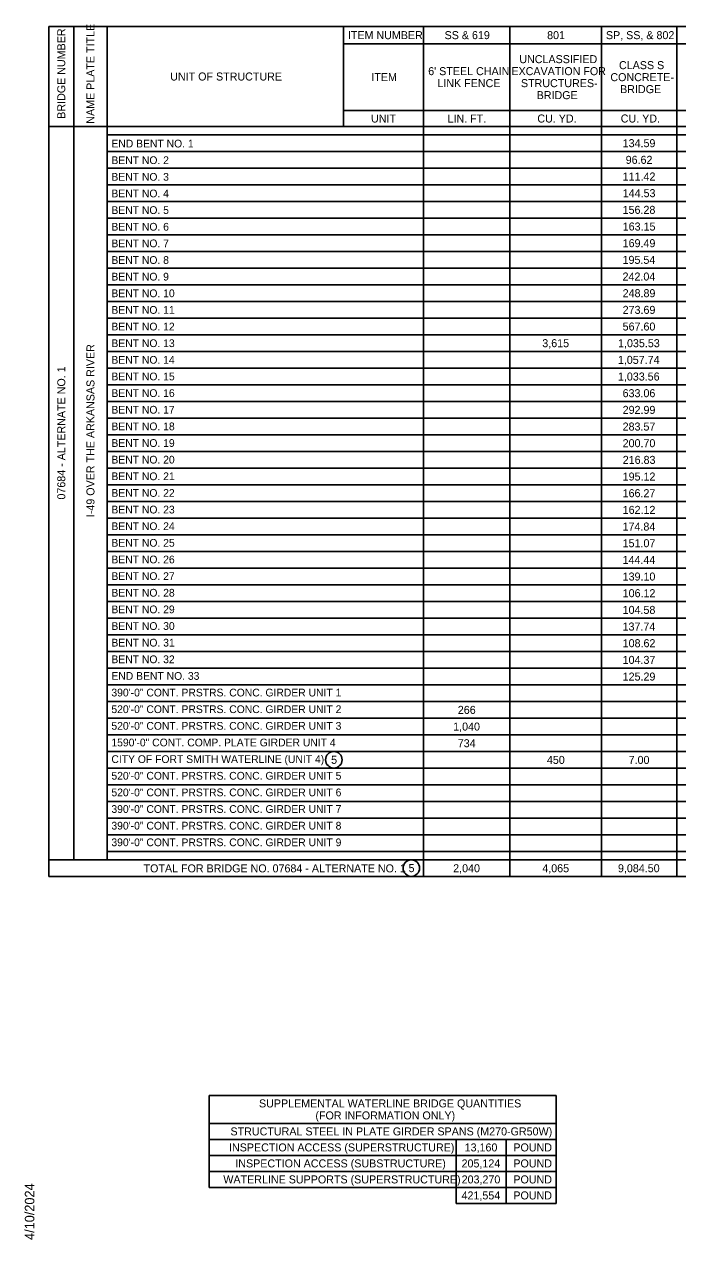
# Model space of a CAD drawing. Extents: x 0.06 to 1.38, y 0.04 to 0.85.
# Drawn here: x 0.06 to 0.468, y 0.079 to 0.838 of the extents above; entities that cross this region are included whole.
import ezdxf

# ---------------------------------------------------------------- set-up
doc = ezdxf.new("R2010")
doc.units = 0
for name, color, linetype in [('R_Shade By Others', 7, 'Continuous'), ('R_Survey Control', 7, 'Continuous'), ('R_Wall', 7, 'Continuous')]:
    doc.layers.add(name, color=color, linetype=linetype)

msp = doc.modelspace()

# ---------------------------------------------------------------- linework, layer by layer
at = {"layer": 'R_Survey Control'}
for p, q in [((0.07508, 0.3057), (0.07508, 0.83695)), ((0.07508, 0.83695), (1.38207, 0.83695)), ((0.09071, 0.31612), (0.09071, 0.83695)), ((0.11154, 0.31612), (0.11154, 0.83695)), ((0.11154, 0.77445), (0.11154, 0.83695)), ((0.2593, 0.77445), (0.2593, 0.83695)), ((0.30915, 0.83695), (0.30915, 0.3057)), ((0.36311, 0.83695), (0.36311, 0.3057)), ((0.4204, 0.83695), (0.4204, 0.3057)), ((0.46733, 0.83695), (0.46733, 0.3057)), ((0.2593, 0.78445), (1.38207, 0.78445)), ((0.07508, 0.77445), (1.38207, 0.77445)), ((0.11154, 0.76924), (1.38207, 0.76924)), ((0.11154, 0.75883), (1.38207, 0.75883)), ((0.11154, 0.74841), (1.38207, 0.74841)), ((0.11154, 0.73799), (1.38207, 0.73799)), ((0.11154, 0.72758), (1.38207, 0.72758)), ((0.11154, 0.71716), (1.38207, 0.71716)), ((0.11154, 0.70674), (1.38207, 0.70674)), ((0.11154, 0.69633), (1.38207, 0.69633)), ((0.11154, 0.68591), (1.38207, 0.68591)), ((0.11154, 0.67549), (1.38207, 0.67549)), ((0.11154, 0.66508), (1.38207, 0.66508)), ((0.11154, 0.65466), (1.38207, 0.65466)), ((0.11154, 0.64424), (1.38207, 0.64424)), ((0.11154, 0.63383), (1.38207, 0.63383)), ((0.11154, 0.62341), (1.38207, 0.62341)), ((0.11154, 0.61299), (1.38207, 0.61299)), ((0.11154, 0.60258), (1.38207, 0.60258)), ((0.11154, 0.59216), (1.38207, 0.59216)), ((0.11154, 0.58174), (1.38207, 0.58174)), ((0.11154, 0.57133), (1.38207, 0.57133)), ((0.11154, 0.56091), (1.38207, 0.56091)), ((0.11154, 0.55049), (1.38207, 0.55049)), ((0.11154, 0.54008), (1.38207, 0.54008)), ((0.11154, 0.52966), (1.38207, 0.52966)), ((0.11154, 0.51924), (1.38207, 0.51924)), ((0.11154, 0.50883), (1.38207, 0.50883)), ((0.11154, 0.49841), (1.38207, 0.49841)), ((0.11154, 0.48799), (1.38207, 0.48799)), ((0.11154, 0.47758), (1.38207, 0.47758)), ((0.11154, 0.46716), (1.38207, 0.46716)), ((0.11154, 0.45674), (1.38207, 0.45674)), ((0.11154, 0.44633), (1.38207, 0.44633)), ((0.11154, 0.43591), (1.38207, 0.43591)), ((0.11154, 0.42549), (1.38207, 0.42549)), ((0.11154, 0.41508), (1.38207, 0.41508)), ((0.11154, 0.40466), (1.38207, 0.40466)), ((0.11154, 0.39424), (1.38207, 0.39424)), ((0.11154, 0.38383), (1.38207, 0.38383)), ((0.11154, 0.37341), (1.38207, 0.37341)), ((0.11154, 0.36299), (1.38207, 0.36299)), ((0.11154, 0.35258), (1.38207, 0.35258)), ((0.11154, 0.34216), (1.38207, 0.34216)), ((0.11154, 0.33174), (1.38207, 0.33174)), ((0.11154, 0.32133), (1.38207, 0.32133)), ((0.07508, 0.31612), (1.38207, 0.31612)), ((0.07508, 0.3057), (1.38207, 0.3057)), ((0.17537, 0.16895), (0.17537, 0.11145)), ((0.17537, 0.16895), (0.39204, 0.16895)), ((0.39204, 0.16895), (0.39204, 0.10145)), ((0.17537, 0.15145), (0.39204, 0.15145)), ((0.17537, 0.14145), (0.39204, 0.14145)), ((0.32954, 0.14145), (0.32954, 0.10145)), ((0.36079, 0.14145), (0.36079, 0.10145)), ((0.17537, 0.13145), (0.39204, 0.13145)), ((0.17537, 0.12145), (0.39204, 0.12145)), ((0.17537, 0.11145), (0.39204, 0.11145)), ((0.32954, 0.10145), (0.39204, 0.10145))]:
    msp.add_line(p, q, dxfattribs=at)
msp.add_lwpolyline([(0.2593, 0.82612), (0.30758, 0.82612), (0.41883, 0.82612), (0.46733, 0.82612), (0.509, 0.82612), (0.60403, 0.82612), (0.64048, 0.82612), (0.68476, 0.82612), (0.72903, 0.82612), (0.79673, 0.82612), (0.84248, 0.82612), (0.89457, 0.82612), (0.99353, 0.82612), (1.05082, 0.82612), (1.11332, 0.82612), (1.1813, 0.82612), (1.249, 0.82612), (1.249, 0.82612), (1.30109, 0.82612), (1.38207, 0.82612)], dxfattribs=at)
at = {"layer": 'R_Wall'}
for p, q in [((0.07508, 0.77445), (0.09071, 0.77445)), ((0.09071, 0.77445), (0.11154, 0.77445))]:
    msp.add_line(p, q, dxfattribs=at)
for centre in [(0.25316, 0.37868), (0.30155, 0.31097)]:
    msp.add_circle(centre, 0.00515, dxfattribs=at)

# ---------------------------------------------------------------- texts
at = {"layer": 'R_Shade By Others'}
msp.add_text('4/10/2024', height=0.00595, rotation=89.99995, dxfattribs=at).set_placement((0.06607, 0.0786))
at = {"layer": 'R_Survey Control'}
for s, p in [('NAME PLATE TITLE', (0.10362, 0.77619)), ('BRIDGE NUMBER', (0.0854, 0.77929)), ('I-49 OVER THE ARKANSAS RIVER', (0.10362, 0.53031)), ('07684 - ALTERNATE NO. 1', (0.0854, 0.54132))]:
    msp.add_text(s, height=0.005, rotation=90, dxfattribs=at).set_placement(p)
for s, height, p in [('ITEM NUMBER', 0.005, (0.26194, 0.82904)), ('SS & 619', 0.005, (0.32235, 0.82904)), ('801', 0.005, (0.3864, 0.82904)), ('SP, SS, & 802', 0.005, (0.42313, 0.82904)), ('UNCLASSIFIED', 0.005, (0.36903, 0.81404)), ('CLASS S ', 0.005, (0.4313, 0.81029)), ('UNIT OF STRUCTURE', 0.005, (0.15095, 0.8032)), ('ITEM', 0.005, (0.27661, 0.80279)), ("6' STEEL CHAIN", 0.005, (0.31212, 0.80654)), ('EXCAVATION FOR ', 0.005, (0.36408, 0.80654)), ('CONCRETE-', 0.005, (0.42591, 0.80279)), ('LINK FENCE', 0.005, (0.31785, 0.79904)), ('STRUCTURES-', 0.005, (0.37004, 0.79904)), ('BRIDGE', 0.005, (0.43198, 0.79529)), ('BRIDGE', 0.005, (0.37987, 0.79154)), ('UNIT', 0.005, (0.27638, 0.77695)), ('LIN. FT.', 0.005, (0.32421, 0.77695)), ('CU. YD.', 0.005, (0.38029, 0.77695)), ('CU. YD.', 0.005, (0.4324, 0.77695)), ('END BENT NO. 1', 0.0048358, (0.11421, 0.76137)), ('134.59', 0.005, (0.43359, 0.76154)), ('BENT NO. 2', 0.004836, (0.11421, 0.75098)), ('96.62', 0.005, (0.43547, 0.75112)), ('BENT NO. 3', 0.004836, (0.11421, 0.74058)), ('111.42', 0.005, (0.4336, 0.7407)), ('BENT NO. 4', 0.004836, (0.11421, 0.73018)), ('144.53', 0.005, (0.43364, 0.73029)), ('BENT NO. 5', 0.004836, (0.11421, 0.71979)), ('156.28', 0.005, (0.43357, 0.71987)), ('BENT NO. 6', 0.004836, (0.11421, 0.70939)), ('163.15', 0.005, (0.43362, 0.70945)), ('BENT NO. 7', 0.004836, (0.11421, 0.69899)), ('169.49', 0.005, (0.43359, 0.69904)), ('BENT NO. 8', 0.004836, (0.11421, 0.6886)), ('195.54', 0.005, (0.43353, 0.68862)), ('BENT NO. 9', 0.004836, (0.11421, 0.6782)), ('242.04', 0.005, (0.43353, 0.6782)), ('BENT NO. 10', 0.0048358, (0.11421, 0.6678)), ('248.89', 0.005, (0.43359, 0.66779)), ('BENT NO. 11', 0.0048358, (0.11421, 0.65741)), ('273.69', 0.005, (0.43359, 0.65737)), ('BENT NO. 12', 0.0048358, (0.11421, 0.64701)), ('567.60', 0.005, (0.43358, 0.64695)), ('BENT NO. 13', 0.0048358, (0.11421, 0.63661)), ('3,615', 0.005, (0.38339, 0.63654)), ('1,035.53', 0.005, (0.43072, 0.63654)), ('BENT NO. 14', 0.0048358, (0.11421, 0.62621)), ('1,057.74', 0.005, (0.43061, 0.62612)), ('BENT NO. 15', 0.0048358, (0.11421, 0.61582)), ('1,033.56', 0.005, (0.43064, 0.6157)), ('BENT NO. 16', 0.0048358, (0.11421, 0.60542)), ('633.06', 0.005, (0.43356, 0.60529)), ('BENT NO. 17', 0.0048358, (0.11421, 0.59502)), ('292.99', 0.005, (0.43359, 0.59487)), ('BENT NO. 18', 0.0048358, (0.11421, 0.58463)), ('283.57', 0.005, (0.43357, 0.58445)), ('BENT NO. 19', 0.0048358, (0.11421, 0.57423)), ('200.70', 0.005, (0.43358, 0.57404)), ('BENT NO. 20', 0.0048358, (0.11421, 0.56383)), ('216.83', 0.005, (0.43364, 0.56362)), ('BENT NO. 21', 0.0048358, (0.11421, 0.55344)), ('195.12', 0.005, (0.4336, 0.5532)), ('BENT NO. 22', 0.0048358, (0.11421, 0.54304)), ('166.27', 0.005, (0.43357, 0.54279)), ('BENT NO. 23', 0.0048358, (0.11421, 0.53264)), ('162.12', 0.005, (0.4336, 0.53237)), ('BENT NO. 24', 0.0048358, (0.11421, 0.52225)), ('174.84', 0.005, (0.43353, 0.52195)), ('BENT NO. 25', 0.0048358, (0.11421, 0.51185)), ('151.07', 0.005, (0.43357, 0.51154)), ('BENT NO. 26', 0.0048358, (0.11421, 0.50145)), ('144.44', 0.005, (0.43353, 0.50112)), ('BENT NO. 27', 0.0048358, (0.11421, 0.49105)), ('139.10', 0.005, (0.43358, 0.4907)), ('BENT NO. 28', 0.0048358, (0.11421, 0.48066)), ('106.12', 0.005, (0.4336, 0.48029)), ('BENT NO. 29', 0.0048358, (0.11421, 0.47026)), ('104.58', 0.005, (0.43357, 0.46987)), ('BENT NO. 30', 0.0048358, (0.11421, 0.45986)), ('137.74', 0.005, (0.43353, 0.45945)), ('BENT NO. 31', 0.0048358, (0.11421, 0.44947)), ('108.62', 0.005, (0.4336, 0.44904)), ('BENT NO. 32', 0.0048358, (0.11421, 0.43907)), ('104.37', 0.005, (0.43357, 0.43862)), ('END BENT NO. 33', 0.0048358, (0.11421, 0.42867)), ('125.29', 0.005, (0.43359, 0.4282)), ('390\'-0" CONT. PRSTRS. CONC. GIRDER UNIT 1', 0.0048358, (0.11421, 0.41828)), ('520\'-0" CONT. PRSTRS. CONC. GIRDER UNIT 2', 0.0048358, (0.11421, 0.40788)), ('266', 0.005, (0.33061, 0.40737)), ('520\'-0" CONT. PRSTRS. CONC. GIRDER UNIT 3', 0.0048358, (0.11421, 0.39748)), ('1,040', 0.005, (0.32772, 0.39695)), ('1590\'-0" CONT. COMP. PLATE GIRDER UNIT 4', 0.0048358, (0.11421, 0.38708)), ('734', 0.005, (0.33058, 0.38654)), ('CITY OF FORT SMITH WATERLINE (UNIT 4)', 0.0048358, (0.11421, 0.37669)), ('450', 0.005, (0.38626, 0.37612)), ('7.00', 0.005, (0.43733, 0.37612)), ('520\'-0" CONT. PRSTRS. CONC. GIRDER UNIT 5', 0.0048358, (0.11421, 0.36629)), ('520\'-0" CONT. PRSTRS. CONC. GIRDER UNIT 6', 0.0048358, (0.11421, 0.35589)), ('390\'-0" CONT. PRSTRS. CONC. GIRDER UNIT 7', 0.0048358, (0.11421, 0.3455)), ('390\'-0" CONT. PRSTRS. CONC. GIRDER UNIT 8', 0.0048358, (0.11421, 0.3351)), ('390\'-0" CONT. PRSTRS. CONC. GIRDER UNIT 9', 0.0048358, (0.11421, 0.3247)), ('TOTAL FOR BRIDGE NO. 07684 - ALTERNATE NO. 1', 0.005, (0.13429, 0.30834)), ('2,040', 0.005, (0.32772, 0.30841)), ('4,065', 0.005, (0.38339, 0.30841)), ('9,084.50', 0.005, (0.43066, 0.30841)), ('SUPPLEMENTAL WATERLINE BRIDGE QUANTITIES', 0.005, (0.2064, 0.16145)), ('(FOR INFORMATION ONLY)', 0.005, (0.24166, 0.15395)), ('STRUCTURAL STEEL IN PLATE GIRDER SPANS (M270-GR50W)', 0.005, (0.1886, 0.14395)), ('INSPECTION ACCESS (SUPERSTRUCTURE)', 0.005, (0.18768, 0.13395)), ('13,160', 0.005, (0.33488, 0.13395)), ('POUND', 0.005, (0.36531, 0.13395)), ('INSPECTION ACCESS (SUBSTRUCTURE)', 0.005, (0.19161, 0.12395)), ('205,124', 0.005, (0.33295, 0.12395)), ('POUND', 0.005, (0.36531, 0.12395)), ('WATERLINE SUPPORTS (SUPERSTRUCTURE)', 0.005, (0.18413, 0.11395)), ('203,270', 0.005, (0.333, 0.11395)), ('POUND', 0.005, (0.36531, 0.11395)), ('421,554', 0.005, (0.33295, 0.10395)), ('POUND', 0.005, (0.36531, 0.10395))]:
    msp.add_text(s, height=height, dxfattribs=at).set_placement(p)
at = {"layer": 'R_Wall'}
for p in [(0.25146, 0.37618), (0.29985, 0.30847)]:
    msp.add_text('5', height=0.005, dxfattribs=at).set_placement(p)

doc.saveas('drawing.dxf')
